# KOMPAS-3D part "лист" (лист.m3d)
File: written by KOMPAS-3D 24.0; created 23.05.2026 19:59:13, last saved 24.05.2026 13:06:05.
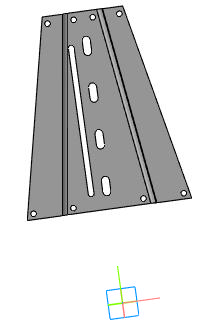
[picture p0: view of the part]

Document properties: Автор: R2D2; Полное имя файла: E:\Работа\Зайцев\GVKR1331M-1W-Fb-2P Задвижка шиберная с выдвижным штоком DN.ru Ду50-300 Ру16-10-6 с пневмоприводом\исходные материалы\DN200\лист.m3d

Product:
- Part/product: лист
    Масса: 2.594022
    Раздел спецификации: Прочие изделия
    Примечание: D040-08800

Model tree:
1. Эскиз:6  (with: Грань.Элемент выдавливания:15, Ребро.Элемент выдавливания:15)
2. Эскиз:7  (with: Грань.Элемент выдавливания:6, Ребро.Элемент выдавливания:6, Ребро.Элемент выдавливания:12)
3. Линейчатая обечайка:1
     Расстояние 1 = 10; Толщина листового тела = 4; Коэффициент = 0.5
4. Сгиб(1) - Линейчатая обечайка:1
     Радиус сгиба = 5; Коэффициент = 0.5; Величина сгиба = 5
5. Сгиб(2) - Линейчатая обечайка:1
     Радиус сгиба = 5; Коэффициент = 0.5; Величина сгиба = 5
6. Сгиб(3) - Линейчатая обечайка:1
     Радиус сгиба = 5; Коэффициент = 0.5; Величина сгиба = 5
7. Сгиб(4) - Линейчатая обечайка:1
     Радиус сгиба = 5; Коэффициент = 0.5; Величина сгиба = 5; Зазор = 1; Угол = 360; Параметр U, % = 100; Длина = 149
8. Эскиз:8  (with: Грань.Линейчатая обечайка:1, Ребро.Линейчатая обечайка:1)
9. Отверстие в листовом теле:1  (with: Грань.Линейчатая обечайка:1, Ребро.Линейчатая обечайка:1)
     Глубина выреза = 10; Расстояние 1 = 10; Расстояние 2 = 10
10. Отверстие в листовом теле:2  (with: Грань.Линейчатая обечайка:1, Ребро.Линейчатая обечайка:1)
     Глубина выреза = 10; Расстояние 1 = -10; Расстояние 2 = 10
11. Отверстие в листовом теле:3  (with: Грань.Линейчатая обечайка:1, Ребро.Линейчатая обечайка:1)
     Глубина выреза = 10; Расстояние 1 = -130.618; Расстояние 2 = 10
12. Отверстие в листовом теле:4  (with: Грань.Линейчатая обечайка:1, Ребро.Линейчатая обечайка:1)
     Глубина выреза = 10; Расстояние 1 = -49.1161; Расстояние 2 = 10
13. Отверстие в листовом теле:5  (with: Грань.Линейчатая обечайка:1, Ребро.Линейчатая обечайка:1)
     Глубина выреза = 10; Расстояние 1 = 10; Расстояние 2 = 331
14. Отверстие в листовом теле:6  (with: Грань.Линейчатая обечайка:1, Ребро.Линейчатая обечайка:1)
     Глубина выреза = 10; Расстояние 1 = -10; Расстояние 2 = 331
15. Отверстие в листовом теле:7  (with: Грань.Линейчатая обечайка:1, Ребро.Линейчатая обечайка:1)
     Глубина выреза = 10; Расстояние 1 = -42.8543; Расстояние 2 = 331
16. Отверстие в листовом теле:8  (with: Грань.Линейчатая обечайка:1, Ребро.Линейчатая обечайка:1)
     Глубина выреза = 10; Расстояние 1 = -25.4199; Расстояние 2 = 331
17. Эскиз:9  (with: Грань.Линейчатая обечайка:1, Ребро.Линейчатая обечайка:1)
18. Эскиз:10  (with: Грань.Линейчатая обечайка:1, Ребро.Линейчатая обечайка:1)
19. Вырез в листовом теле:1
     Глубина выреза = 10
20. Вырез в листовом теле:2
     Глубина выреза = 10
21. Массив по сетке:1  (with: Вырез в листовом теле:2, Эскиз:9, Эскиз:10)  (4 pattern instances)
     Угол раствора = 90; Геометрический массив = 128

Expressions: 2*h; v1424-100
Referenced files in E:\Работа\Зайцев\GVKR1331M-1W-Fb-2P Задвижка шиберная с выдвижным штоком DN.ru Ду50-300 Ру16-10-6 с пневмоприводом\исходные материалы\DN200\: GVKR1331M-1W-Fb-2P Задвижка шиберная с выдвижным штоком DN.ru Ду200 Ру10.a3d
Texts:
  Затвор дисковый DN.ru Ду Ру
